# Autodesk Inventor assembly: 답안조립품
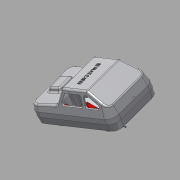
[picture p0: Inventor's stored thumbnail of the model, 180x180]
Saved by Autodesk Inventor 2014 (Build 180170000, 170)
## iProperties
Created: 2007-09
Part Number: 답안조립품
Document SubType Name: Assembly
Designer: Administrator
Author: Administrator
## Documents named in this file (7)
- C:\Documents and Settings\Administrator\바탕 화면\450508V1018\450508V1018\답안조립품.iam
- C:\Documents and Settings\Administrator\바탕 화면\450508V1018\450508V1018\본체.ipt
- C:\Documents and Settings\Administrator\바탕 화면\450508V1018\450508V1018\커버.ipt
- C:\Documents and Settings\Administrator\바탕 화면\450508V1018\450508V1018\바퀴고정부.ipt
- C:\Documents and Settings\Administrator\바탕 화면\450508V1018\450508V1018\바퀴.ipt
- C:\Documents and Settings\Administrator\바탕 화면\450508V1018\450508V1018\M4x10.ipt
- C:\Documents and Settings\Administrator\바탕 화면\450508V1018\450508V1018\M2x4.ipt
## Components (20 placed, 2 different names)
1. M4x10:1
2. M4x10:2
3. M4x10:3
4. M4x10:4
5. M2x4:1
6. M2x4:2
7. M2x4:3
8. M2x4:4
9. M2x4:5
10. M2x4:6
11. M2x4:7
12. M2x4:8
13. M2x4:9
14. M2x4:10
15. M2x4:11
16. M2x4:12
17. M2x4:13
18. M2x4:14
19. M2x4:15
20. M2x4:16
